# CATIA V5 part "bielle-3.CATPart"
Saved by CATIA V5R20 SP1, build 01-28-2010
Part number: bielle-3
Bounding box of the stored display mesh (mm): x -354.681 to 205.319, y -24.207 to 5.793, z 0 to 30
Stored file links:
  C:\Users\Manon\Desktop\IAO\Pieces\bielle-3.CATPart
  C:\Users\Manon\Desktop\IAO\assemblage\Assemblage_rlanglais.CATProduct
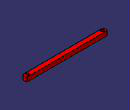
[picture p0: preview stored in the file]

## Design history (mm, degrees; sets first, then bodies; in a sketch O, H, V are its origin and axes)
External parameters (linked from other documents)
  External.bielle_3 = 520 mm
Body1 (main body)
  Sketch1 on xy-plane, origin (0, 0, 0), H (1, 0, 0), V (0, 1, 0)
    line L1 (-354.6806, 5.7934) -> (205.3194, 5.7934)
    line L2 (205.3194, 5.7934) -> (205.3194, -24.2066)
    line L3 (205.3194, -24.2066) -> (-354.6806, -24.2066)
    line L4 (-354.6806, -24.2066) -> (-354.6806, 5.7934)
    circle A1 centre (185.3194, -9.2066) radius 10
    point P5 (185.3194, -9.2066)
    point P6 (189.2231, 0)
    circle A2 centre (-334.6806, -9.2066) radius 10
    point P7 (-334.6806, -9.2066)
    point P8 (-330.7769, 0)
    length L2 = 30
    length L1 = 560
    radius A2 = 10
    radius A1 = 10
    distance P5 L3 = 15
    distance P5 L2 = 20
    distance P7 L3 = 15
    distance P5 P7 = 520 {= External.bielle_3}
    horizontal: L1 H, L3 H
    vertical: L2 V, L4 V
    coincidence: A1 P6, P6 H, A2 P8, P8 H
  Pad1: profile Sketch1, direction (0, 0, 1), length 30
  Fillet1: radius 5, on edge [face of Pad1 from Sketch1.L2 | face of Pad1 from Sketch1.L3]; edge [face of Pad1 from Sketch1.L1 | face of Pad1 from Sketch1.L2]; edge [face of Pad1 from Sketch1.L3 | face of Pad1 from Sketch1.L4]; edge [face of Pad1 from Sketch1.L4 | face of Pad1 from Sketch1.L1]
